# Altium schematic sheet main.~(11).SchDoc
size A
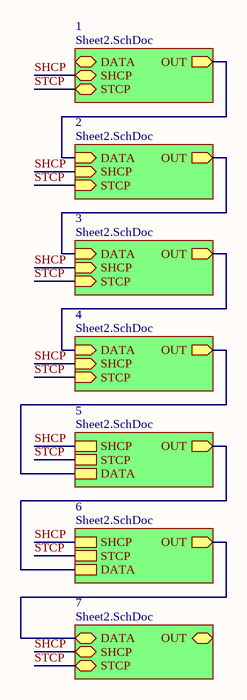
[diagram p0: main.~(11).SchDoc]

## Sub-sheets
1 = Sheet2.SchDoc: DATA, SHCP, STCP, OUT (out)
2 = Sheet2.SchDoc: DATA (in), SHCP (in), STCP (in), OUT (out)
3 = Sheet2.SchDoc: DATA (in), SHCP (in), STCP (in), OUT (out)
4 = Sheet2.SchDoc: DATA (in), SHCP (in), STCP (in), OUT (out)
5 = Sheet2.SchDoc: SHCP, STCP, DATA, OUT (out)
6 = Sheet2.SchDoc: SHCP, STCP, DATA, OUT (out)
7 = Sheet2.SchDoc: DATA, SHCP, STCP, OUT

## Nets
SHCP: sheet 1/SHCP, sheet 2/SHCP, sheet 3/SHCP, sheet 4/SHCP, sheet 5/SHCP, sheet 6/SHCP, sheet 7/SHCP
STCP: sheet 1/STCP, sheet 2/STCP, sheet 3/STCP, sheet 4/STCP, sheet 5/STCP, sheet 6/STCP, sheet 7/STCP
(unnamed): sheet 1/OUT, sheet 2/DATA
(unnamed): sheet 2/OUT, sheet 3/DATA  [a separate net that carries the same name]
(unnamed): sheet 3/OUT, sheet 4/DATA  [a separate net that carries the same name]
(unnamed): sheet 4/OUT, sheet 5/DATA  [a separate net that carries the same name]
(unnamed): sheet 5/OUT, sheet 6/DATA  [a separate net that carries the same name]
(unnamed): sheet 6/OUT, sheet 7/DATA  [a separate net that carries the same name]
